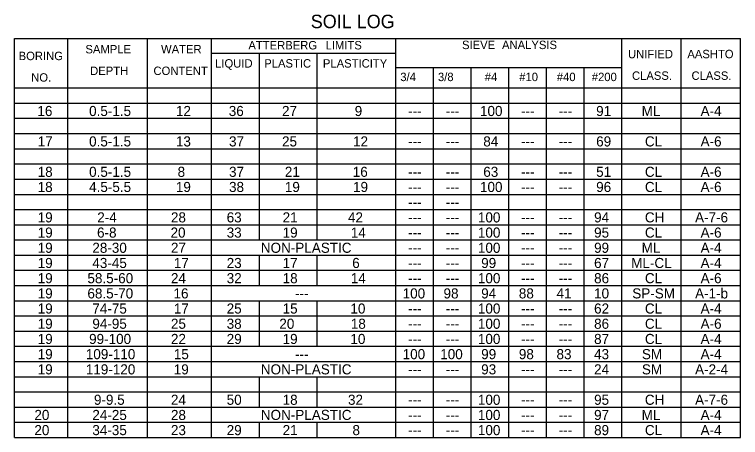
# Model space of a CAD drawing. Extents: x 1197542 to 1207464, y 185022 to 237324.
# Drawn here: x 1207185.3 to 1207293.3, y 185142.6 to 185205.5 of the extents above; entities that cross this region are included whole.
import ezdxf

# ---------------------------------------------------------------- set-up
doc = ezdxf.new("R2010")
doc.units = 0
doc.layers.add('R_No Plot', color=7, linetype='Continuous')

msp = doc.modelspace()

# ---------------------------------------------------------------- linework, layer by layer
at = {"layer": 'R_No Plot'}
for p, q in [((1207185.34, 185201.94), (1207185.34, 185201.94)), ((1207185.34, 185201.94), (1207293.3, 185201.94)), ((1207185.34, 185142.64), (1207185.34, 185201.94)), ((1207193.27, 185142.64), (1207193.27, 185201.94)), ((1207205.11, 185142.64), (1207205.11, 185201.94)), ((1207214.61, 185142.64), (1207214.61, 185201.94)), ((1207242.05, 185142.64), (1207242.05, 185201.94)), ((1207275.64, 185142.64), (1207275.64, 185201.94)), ((1207284.47, 185142.64), (1207284.47, 185201.94)), ((1207293.3, 185142.64), (1207293.3, 185201.94)), ((1207214.61, 185199.78), (1207242.05, 185199.78)), ((1207221.77, 185172.01), (1207221.77, 185199.78)), ((1207230.35, 185172.01), (1207230.35, 185199.78)), ((1207242.05, 185197.62), (1207275.64, 185197.62)), ((1207247.65, 185142.64), (1207247.65, 185197.62)), ((1207253.25, 185142.64), (1207253.25, 185197.62)), ((1207258.84, 185142.64), (1207258.84, 185197.62)), ((1207264.44, 185142.64), (1207264.44, 185197.62)), ((1207270.04, 185142.64), (1207270.04, 185197.62)), ((1207185.34, 185194.6), (1207293.3, 185194.6)), ((1207275.64, 185194.6), (1207293.3, 185194.6)), ((1207185.34, 185192.34), (1207293.3, 185192.34)), ((1207185.34, 185190.08), (1207293.3, 185190.08)), ((1207185.34, 185187.82), (1207293.3, 185187.82)), ((1207185.34, 185185.56), (1207293.3, 185185.56)), ((1207185.34, 185183.3), (1207293.3, 185183.3)), ((1207185.34, 185181.04), (1207293.3, 185181.04)), ((1207185.34, 185178.78), (1207293.3, 185178.78)), ((1207185.34, 185176.53), (1207293.3, 185176.53)), ((1207185.34, 185174.27), (1207293.3, 185174.27)), ((1207185.34, 185172.01), (1207293.3, 185172.01)), ((1207185.34, 185169.75), (1207293.3, 185169.75)), ((1207221.77, 185165.23), (1207221.77, 185169.75)), ((1207230.35, 185165.23), (1207230.35, 185169.75)), ((1207185.34, 185167.49), (1207293.3, 185167.49)), ((1207185.34, 185165.23), (1207293.3, 185165.23)), ((1207185.34, 185162.97), (1207293.3, 185162.97)), ((1207221.77, 185156.2), (1207221.77, 185162.97)), ((1207230.35, 185156.2), (1207230.35, 185162.97)), ((1207185.34, 185160.71), (1207293.3, 185160.71)), ((1207185.34, 185158.46), (1207293.3, 185158.46)), ((1207185.34, 185156.2), (1207293.3, 185156.2)), ((1207185.34, 185153.94), (1207293.3, 185153.94)), ((1207185.34, 185151.68), (1207293.3, 185151.68)), ((1207221.77, 185147.16), (1207221.77, 185151.68)), ((1207230.35, 185147.16), (1207230.35, 185151.68)), ((1207185.34, 185149.42), (1207293.3, 185149.42)), ((1207185.34, 185147.16), (1207293.3, 185147.16)), ((1207185.34, 185144.9), (1207293.3, 185144.9)), ((1207221.77, 185142.64), (1207221.77, 185144.9)), ((1207230.35, 185142.64), (1207230.35, 185144.9)), ((1207185.34, 185142.64), (1207293.3, 185142.64))]:
    msp.add_line(p, q, dxfattribs=at)

# ---------------------------------------------------------------- texts
for s, height, p in [('SOIL LOG', 2, (1207229.39, 185203.48)), ('ATTERBERG', 1.25, (1207220.12, 185200.32)), ('LIMITS', 1.25, (1207231.6, 185200.32)), ('SIEVE', 1.25, (1207251.89, 185200.37)), ('ANALYSIS', 1.25, (1207257.84, 185200.37)), ('BORING', 1.25, (1207185.95, 185198.73)), ('SAMPLE', 1.25, (1207195.88, 185199.73)), ('WATER', 1.25, (1207207.13, 185199.73)), ('UNIFIED', 1.25, (1207276.57, 185199.01)), ('AASHTO', 1.25, (1207285.4, 185199.01)), ('LIQUID', 1.25, (1207215.17, 185197.62)), ('PLASTIC', 1.25, (1207222.48, 185197.62)), ('PLASTICITY', 1.25, (1207231.2, 185197.62)), ('DEPTH', 1.25, (1207196.58, 185196.52)), ('CONTENT', 1.25, (1207206, 185196.52)), ('NO.', 1.25, (1207187.82, 185195.53)), ('3/4', 1.25, (1207242.71, 185195.61)), ('3/8', 1.25, (1207248.31, 185195.61)), ('#4', 1.25, (1207255.27, 185195.61)), ('#10', 1.25, (1207260.4, 185195.61)), ('#40', 1.25, (1207265.99, 185195.61)), ('#200', 1.25, (1207271.19, 185195.61)), ('CLASS.', 1.25, (1207277.17, 185195.8)), ('CLASS.', 1.25, (1207286.02, 185195.8)), ('16', 1.5, (1207188.74, 185190.42)), ('0.5-1.5', 1.5, (1207196.43, 185190.42)), ('12', 1.5, (1207209.34, 185190.42)), ('36', 1.5, (1207217.2, 185190.42)), ('27', 1.5, (1207225.12, 185190.42)), ('9', 1.5, (1207235.93, 185190.42)), ('100', 1.5, (1207254.56, 185190.42)), ('91', 1.5, (1207271.84, 185190.42)), ('ML', 1.5, (1207278.6, 185190.42)), ('A-4', 1.5, (1207287.37, 185190.42)), ('---', 1.5, (1207243.88, 185190.42)), ('---', 1.5, (1207249.48, 185190.42)), ('---', 1.5, (1207260.67, 185190.42)), ('---', 1.5, (1207266.27, 185190.42)), ('17', 1.5, (1207188.78, 185185.9)), ('0.5-1.5', 1.5, (1207196.43, 185185.9)), ('13', 1.5, (1207209.34, 185185.9)), ('37', 1.5, (1207217.24, 185185.9)), ('25', 1.5, (1207225.12, 185185.9)), ('12', 1.5, (1207235.68, 185185.9)), ('84', 1.5, (1207255.05, 185185.9)), ('69', 1.5, (1207271.84, 185185.9)), ('CL', 1.5, (1207279.09, 185185.9)), ('A-6', 1.5, (1207287.37, 185185.9)), ('---', 1.5, (1207243.88, 185185.9)), ('---', 1.5, (1207249.48, 185185.9)), ('---', 1.5, (1207260.67, 185185.9)), ('---', 1.5, (1207266.27, 185185.9)), ('18', 1.5, (1207188.78, 185181.38)), ('0.5-1.5', 1.5, (1207196.43, 185181.38)), ('8', 1.5, (1207209.59, 185181.38)), ('37', 1.5, (1207217.24, 185181.38)), ('21', 1.5, (1207225.54, 185181.38)), ('16', 1.5, (1207235.64, 185181.38)), ('63', 1.5, (1207255.05, 185181.38)), ('51', 1.5, (1207271.84, 185181.38)), ('CL', 1.5, (1207279.09, 185181.38)), ('A-6', 1.5, (1207287.37, 185181.38)), ('---', 1.5, (1207243.88, 185181.38)), ('---', 1.5, (1207249.48, 185181.38)), ('---', 1.5, (1207260.67, 185181.38)), ('---', 1.5, (1207266.27, 185181.38)), ('18', 1.5, (1207188.78, 185179.13)), ('4.5-5.5', 1.5, (1207196.43, 185179.13)), ('19', 1.5, (1207209.33, 185179.13)), ('38', 1.5, (1207217.24, 185179.13)), ('19', 1.5, (1207225.54, 185179.13)), ('19', 1.5, (1207235.68, 185179.13)), ('100', 1.5, (1207254.56, 185179.13)), ('96', 1.5, (1207271.84, 185179.13)), ('CL', 1.5, (1207279.09, 185179.13)), ('A-6', 1.5, (1207287.37, 185179.13)), ('---', 1.5, (1207243.88, 185179.13)), ('---', 1.5, (1207249.48, 185179.13)), ('---', 1.5, (1207260.67, 185179.13)), ('---', 1.5, (1207266.27, 185179.13)), ('---', 1.5, (1207243.88, 185176.87)), ('---', 1.5, (1207249.48, 185176.87)), ('19', 1.5, (1207188.78, 185174.61)), ('2-4', 1.5, (1207197.64, 185174.61)), ('28', 1.5, (1207208.6, 185174.61)), ('63', 1.5, (1207216.89, 185174.61)), ('21', 1.5, (1207225.21, 185174.61)), ('42', 1.5, (1207234.93, 185174.61)), ('---', 1.5, (1207243.88, 185174.61)), ('---', 1.5, (1207249.48, 185174.61)), ('100', 1.5, (1207254.25, 185174.61)), ('---', 1.5, (1207260.67, 185174.61)), ('---', 1.5, (1207266.27, 185174.61)), ('94', 1.5, (1207271.53, 185174.61)), ('CH', 1.5, (1207279.08, 185174.61)), ('A-7-6', 1.5, (1207286.55, 185174.61)), ('19', 1.5, (1207188.78, 185172.35)), ('6-8', 1.5, (1207197.61, 185172.35)), ('20', 1.5, (1207208.54, 185172.35)), ('33', 1.5, (1207216.89, 185172.35)), ('19', 1.5, (1207225.21, 185172.35)), ('14', 1.5, (1207235.35, 185172.35)), ('---', 1.5, (1207243.88, 185172.35)), ('---', 1.5, (1207249.48, 185172.35)), ('100', 1.5, (1207254.25, 185172.35)), ('---', 1.5, (1207260.67, 185172.35)), ('---', 1.5, (1207266.27, 185172.35)), ('95', 1.5, (1207271.53, 185172.35)), ('CL', 1.5, (1207279.09, 185172.35)), ('A-6', 1.5, (1207287.37, 185172.35)), ('19', 1.5, (1207188.78, 185170.09)), ('28-30', 1.5, (1207196.91, 185170.09)), ('27', 1.5, (1207208.6, 185170.09)), ('NON-PLASTIC', 1.5, (1207221.97, 185170.09)), ('100', 1.5, (1207254.25, 185170.09)), ('99', 1.5, (1207271.53, 185170.09)), ('ML', 1.5, (1207278.6, 185170.09)), ('A-4', 1.5, (1207287.37, 185170.09)), ('---', 1.5, (1207243.88, 185170.09)), ('---', 1.5, (1207249.48, 185170.09)), ('---', 1.5, (1207260.67, 185170.09)), ('---', 1.5, (1207266.27, 185170.09)), ('19', 1.5, (1207188.78, 185167.83)), ('43-45', 1.5, (1207196.91, 185167.83)), ('17', 1.5, (1207209.03, 185167.83)), ('23', 1.5, (1207216.89, 185167.83)), ('17', 1.5, (1207225.21, 185167.83)), ('6', 1.5, (1207235.56, 185167.83)), ('99', 1.5, (1207254.74, 185167.83)), ('67', 1.5, (1207271.53, 185167.83)), ('ML-CL', 1.5, (1207277.05, 185167.83)), ('A-4', 1.5, (1207287.37, 185167.83)), ('---', 1.5, (1207243.88, 185167.83)), ('---', 1.5, (1207249.48, 185167.83)), ('---', 1.5, (1207260.67, 185167.83)), ('---', 1.5, (1207266.27, 185167.83)), ('19', 1.5, (1207188.78, 185165.57)), ('58.5-60', 1.5, (1207196.18, 185165.57)), ('24', 1.5, (1207208.6, 185165.57)), ('32', 1.5, (1207216.89, 185165.57)), ('18', 1.5, (1207225.21, 185165.57)), ('14', 1.5, (1207235.35, 185165.57)), ('100', 1.5, (1207254.25, 185165.57)), ('86', 1.5, (1207271.53, 185165.57)), ('CL', 1.5, (1207279.09, 185165.57)), ('A-6', 1.5, (1207287.37, 185165.57)), ('---', 1.5, (1207243.88, 185165.57)), ('---', 1.5, (1207249.48, 185165.57)), ('---', 1.5, (1207260.67, 185165.57)), ('---', 1.5, (1207266.27, 185165.57)), ('19', 1.5, (1207188.78, 185163.31)), ('68.5-70', 1.5, (1207196.18, 185163.31)), ('16', 1.5, (1207208.98, 185163.31)), ('100', 1.5, (1207243.06, 185163.31)), ('98', 1.5, (1207249.14, 185163.31)), ('94', 1.5, (1207254.74, 185163.31)), ('88', 1.5, (1207260.34, 185163.31)), ('41', 1.5, (1207265.94, 185163.31)), ('10', 1.5, (1207271.53, 185163.31)), ('SP-SM', 1.5, (1207277.21, 185163.31)), ('A-1-b', 1.5, (1207286.55, 185163.31)), ('---', 1.5, (1207227.05, 185163.32)), ('19', 1.5, (1207188.78, 185161.06)), ('74-75', 1.5, (1207196.91, 185161.06)), ('17', 1.5, (1207209.03, 185161.06)), ('25', 1.5, (1207216.89, 185161.06)), ('15', 1.5, (1207225.21, 185161.06)), ('10', 1.5, (1207235.29, 185161.06)), ('100', 1.5, (1207254.25, 185161.06)), ('62', 1.5, (1207271.53, 185161.06)), ('CL', 1.5, (1207279.09, 185161.06)), ('A-4', 1.5, (1207287.37, 185161.06)), ('---', 1.5, (1207243.88, 185161.06)), ('---', 1.5, (1207249.48, 185161.06)), ('---', 1.5, (1207260.67, 185161.06)), ('---', 1.5, (1207266.27, 185161.06)), ('19', 1.5, (1207188.78, 185158.8)), ('94-95', 1.5, (1207196.91, 185158.8)), ('25', 1.5, (1207208.6, 185158.8)), ('38', 1.5, (1207216.89, 185158.8)), ('20', 1.5, (1207224.72, 185158.8)), ('18', 1.5, (1207235.35, 185158.8)), ('100', 1.5, (1207254.25, 185158.8)), ('86', 1.5, (1207271.53, 185158.8)), ('CL', 1.5, (1207279.09, 185158.8)), ('A-6', 1.5, (1207287.37, 185158.8)), ('---', 1.5, (1207243.88, 185158.8)), ('---', 1.5, (1207249.48, 185158.8)), ('---', 1.5, (1207260.67, 185158.8)), ('---', 1.5, (1207266.27, 185158.8)), ('19', 1.5, (1207188.78, 185156.54)), ('99-100', 1.5, (1207196.43, 185156.54)), ('22', 1.5, (1207208.6, 185156.54)), ('29', 1.5, (1207216.89, 185156.54)), ('19', 1.5, (1207225.21, 185156.54)), ('10', 1.5, (1207235.29, 185156.54)), ('100', 1.5, (1207254.25, 185156.54)), ('87', 1.5, (1207271.53, 185156.54)), ('CL', 1.5, (1207279.09, 185156.54)), ('A-4', 1.5, (1207287.37, 185156.54)), ('---', 1.5, (1207243.88, 185156.54)), ('---', 1.5, (1207249.48, 185156.54)), ('---', 1.5, (1207260.67, 185156.54)), ('---', 1.5, (1207266.27, 185156.54)), ('19', 1.5, (1207188.78, 185154.28)), ('109-110', 1.5, (1207195.94, 185154.28)), ('15', 1.5, (1207209.03, 185154.28)), ('100', 1.5, (1207243.06, 185154.28)), ('100', 1.5, (1207248.65, 185154.28)), ('99', 1.5, (1207254.74, 185154.28)), ('98', 1.5, (1207260.34, 185154.28)), ('83', 1.5, (1207265.94, 185154.28)), ('43', 1.5, (1207271.53, 185154.28)), ('SM', 1.5, (1207278.64, 185154.28)), ('A-4', 1.5, (1207287.37, 185154.28)), ('---', 1.5, (1207227.05, 185154.28)), ('19', 1.5, (1207188.78, 185152.02)), ('119-120', 1.5, (1207195.94, 185152.02)), ('19', 1.5, (1207209.02, 185152.02)), ('NON-PLASTIC', 1.5, (1207221.97, 185152.02)), ('93', 1.5, (1207254.74, 185152.02)), ('24', 1.5, (1207271.53, 185152.02)), ('SM', 1.5, (1207278.64, 185152.02)), ('A-2-4', 1.5, (1207286.55, 185152.02)), ('---', 1.5, (1207243.88, 185152.02)), ('---', 1.5, (1207249.48, 185152.02)), ('---', 1.5, (1207260.67, 185152.02)), ('---', 1.5, (1207266.27, 185152.02)), ('9-9.5', 1.5, (1207197.15, 185147.5)), ('24', 1.5, (1207208.6, 185147.5)), ('50', 1.5, (1207216.89, 185147.5)), ('18', 1.5, (1207225.21, 185147.5)), ('32', 1.5, (1207234.93, 185147.5)), ('---', 1.5, (1207243.88, 185147.5)), ('---', 1.5, (1207249.48, 185147.5)), ('100', 1.5, (1207254.25, 185147.5)), ('---', 1.5, (1207260.67, 185147.5)), ('---', 1.5, (1207266.27, 185147.5)), ('95', 1.5, (1207271.53, 185147.5)), ('CH', 1.5, (1207279.08, 185147.5)), ('A-7-6', 1.5, (1207286.55, 185147.5)), ('20', 1.5, (1207188.29, 185145.24)), ('24-25', 1.5, (1207196.91, 185145.24)), ('28', 1.5, (1207208.6, 185145.24)), ('NON-PLASTIC', 1.5, (1207221.97, 185145.25)), ('100', 1.5, (1207254.25, 185145.24)), ('97', 1.5, (1207271.53, 185145.24)), ('ML', 1.5, (1207278.6, 185145.24)), ('A-4', 1.5, (1207287.37, 185145.24)), ('---', 1.5, (1207243.88, 185145.24)), ('---', 1.5, (1207249.48, 185145.24)), ('---', 1.5, (1207260.67, 185145.24)), ('---', 1.5, (1207266.27, 185145.24)), ('20', 1.5, (1207188.29, 185142.99)), ('34-35', 1.5, (1207196.91, 185142.99)), ('23', 1.5, (1207208.6, 185142.99)), ('29', 1.5, (1207216.89, 185142.99)), ('21', 1.5, (1207225.21, 185142.99)), ('8', 1.5, (1207235.6, 185142.99)), ('100', 1.5, (1207254.25, 185142.99)), ('89', 1.5, (1207271.53, 185142.99)), ('CL', 1.5, (1207279.09, 185142.99)), ('A-4', 1.5, (1207287.37, 185142.99)), ('---', 1.5, (1207243.88, 185142.99)), ('---', 1.5, (1207249.48, 185142.99)), ('---', 1.5, (1207260.67, 185142.99)), ('---', 1.5, (1207266.27, 185142.99))]:
    msp.add_text(s, height=height, dxfattribs=at).set_placement(p)

doc.saveas('drawing.dxf')
